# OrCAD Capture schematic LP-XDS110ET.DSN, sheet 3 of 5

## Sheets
3 3_EnergyTrace: size A3
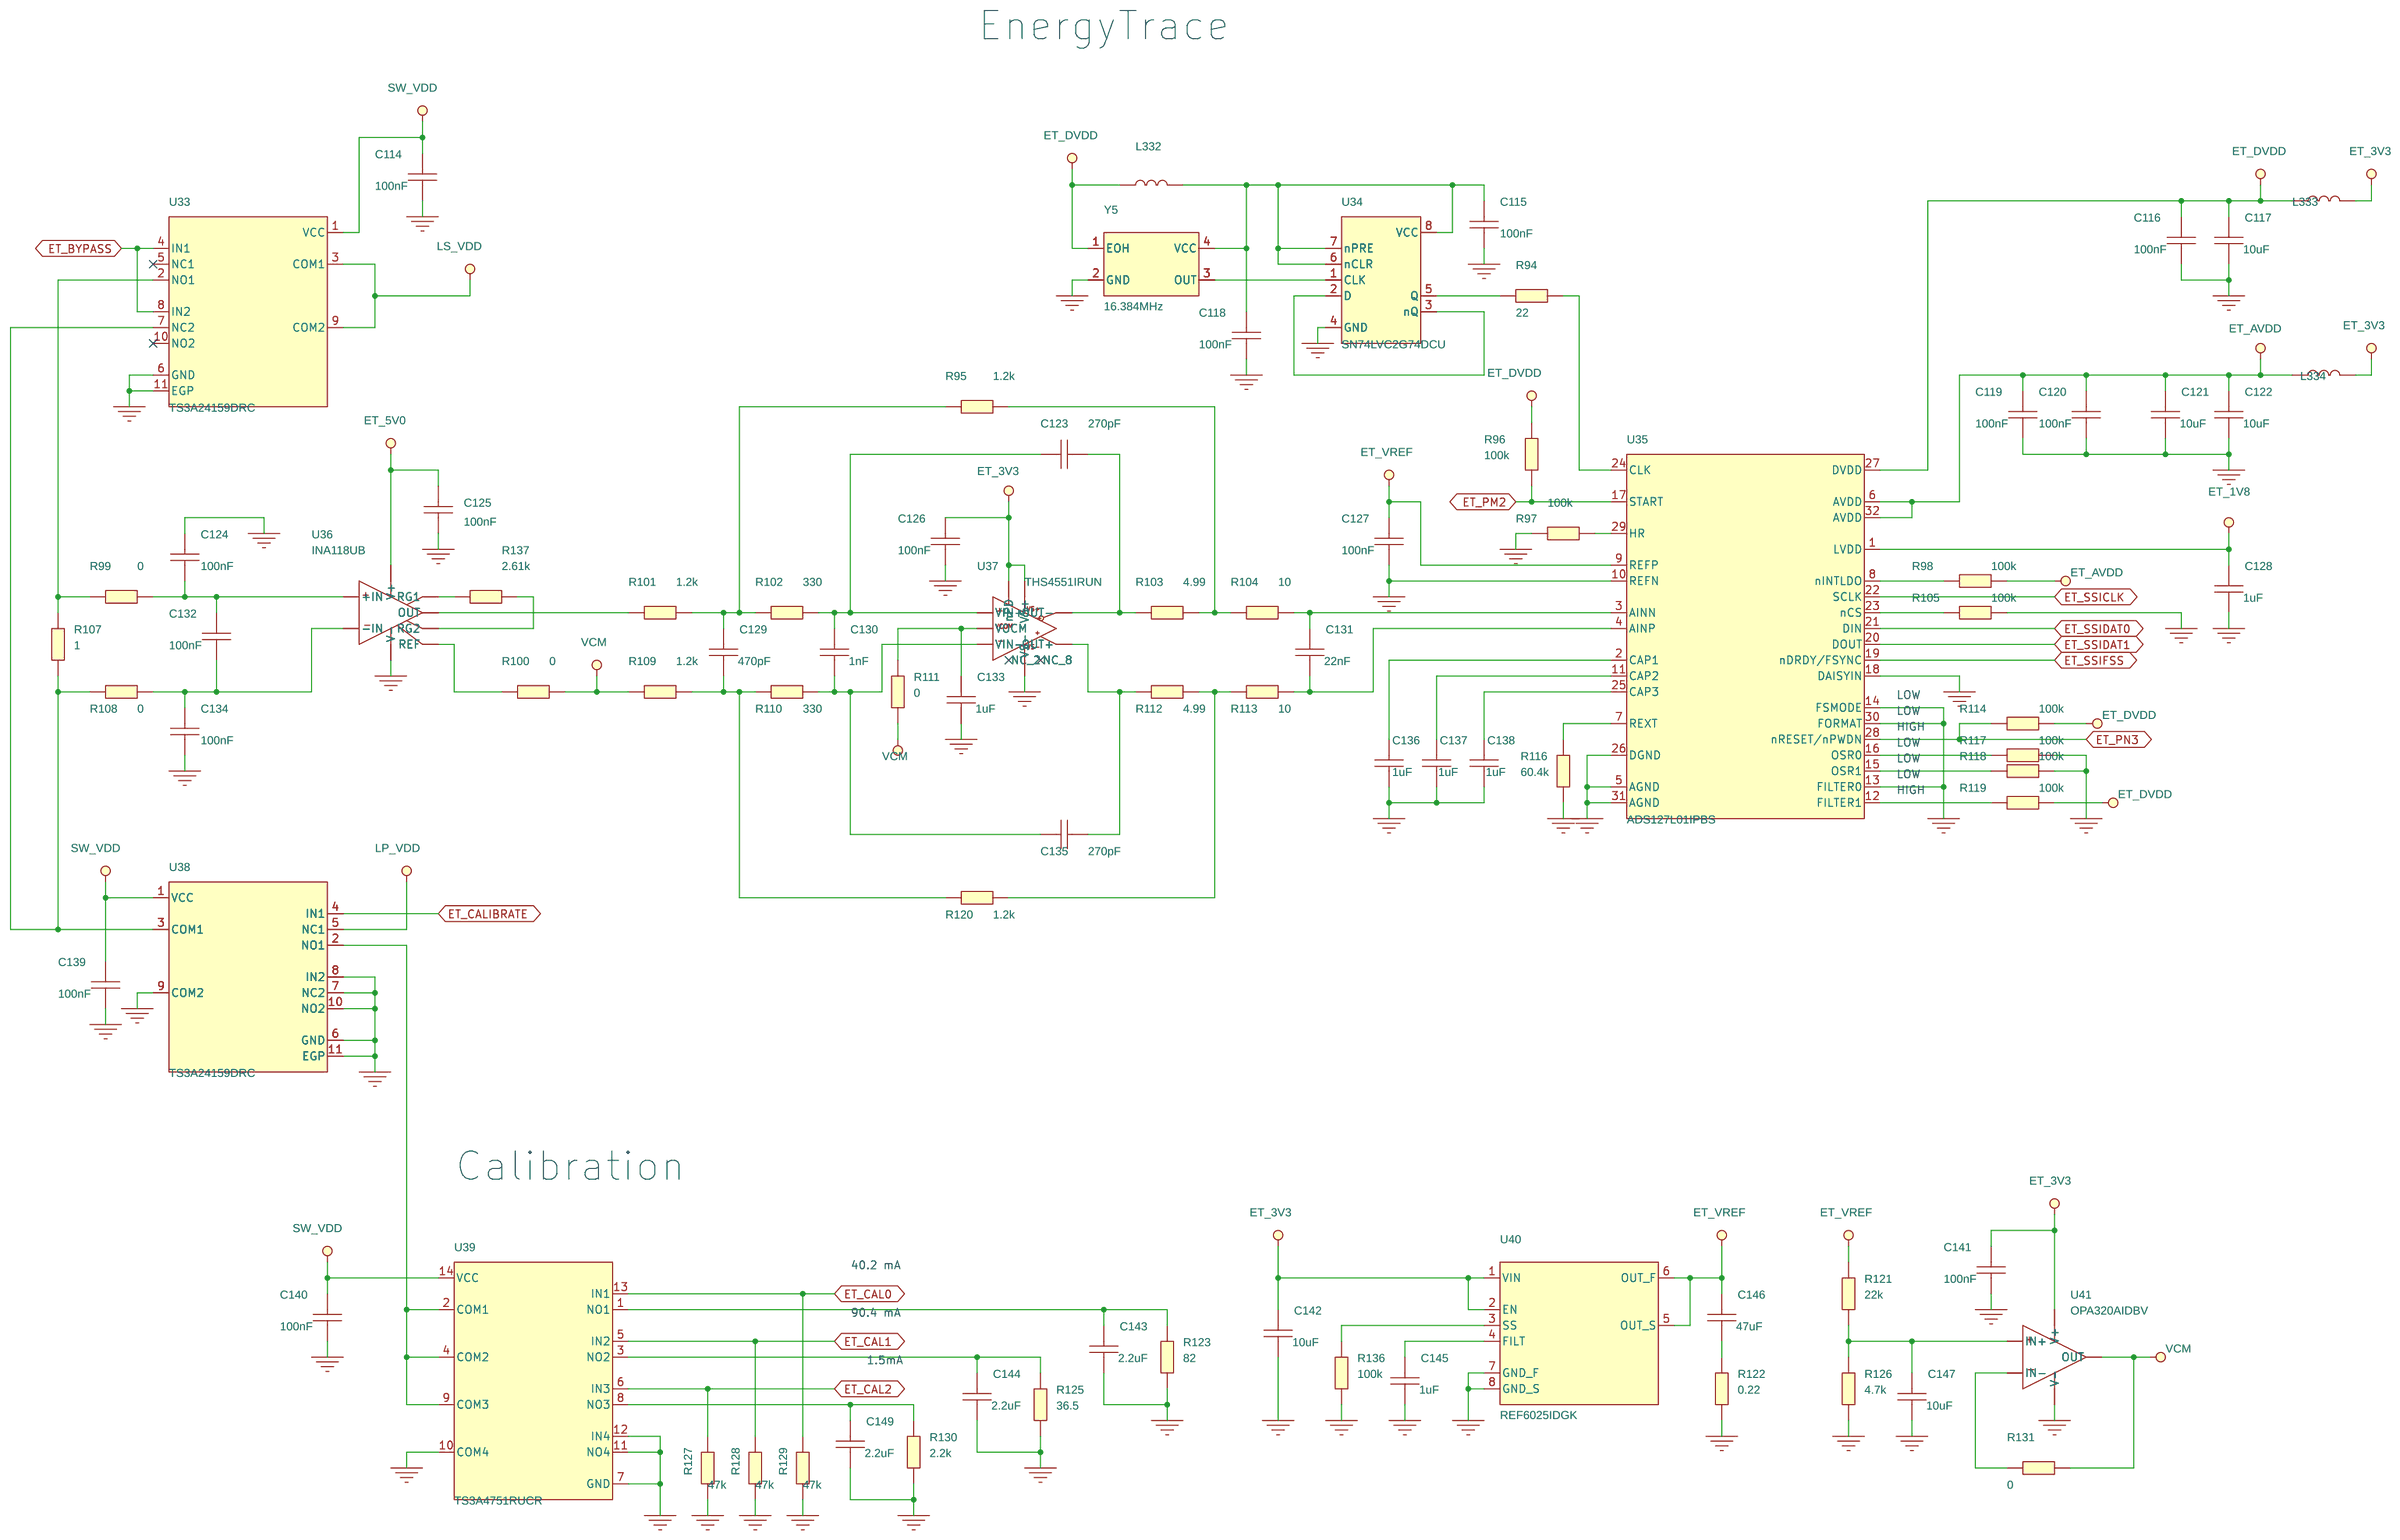
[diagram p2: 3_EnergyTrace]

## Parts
C114  100nF  [CAPC0603X35B2N]
C115  100nF  [CAPC0603X35B2N]
C116  100nF  [CAPC0603X35B2N]
C117  10uF  [CAPC2012X150A2N]
C118  100nF  [CAPC0603X35B2N]
C119  100nF  [CAPC0603X35B2N]
C120  100nF  [CAPC0603X35B2N]
C121  10uF  [CAPC2012X150A2N]
C122  10uF  [CAPC2012X150A2N]
C123  270pF  [CAPC1005X60B2N]
C124  100nF  [CAPC0603X35B2N]
C125  100nF  [CAPC0603X35B2N]
C126  100nF  [CAPC0603X35B2N]
C127  100nF  [CAPC0603X35B2N]
C128  1uF  [CAPC1005X60B2N]
C129  470pF  [CAPC1005X60A2N]
C130  1nF  [CAPC1005X60A2N]
C131  22nF  [CAPC1005X60A2N]
C132  100nF  [CAPC0603X35B2N]
C133  1uF  [CAPC1005X60B2N]
C134  100nF  [CAPC0603X35B2N]
C135  270pF  [CAPC1005X60B2N]
C136  1uF  [CAPC1005X60B2N]
C137  1uF  [CAPC1005X60B2N]
C138  1uF  [CAPC1005X60B2N]
C139  100nF  [CAPC0603X35B2N]
C140  100nF  [CAPC0603X35B2N]
C141  100nF  [CAPC0603X35B2N]
C142  10uF  [CAPC2012X150A2N]
C143  2.2uF  [CAPC1005X60A2N]
C144  2.2uF  [CAPC1005X60A2N]
C145  1uF  [CAPC1005X60B2N]
C146  47uF  [CAPC2012X150A2N]
C147  10uF  [CAPC2012X150A2N]
C149  2.2uF  [CAPC1005X60A2N]
L332  BLM21PG221SN1  [FILC2012X110A2N]
L333  BLM21PG221SN1  [FILC2012X110A2N]
L334  BLM21PG221SN1  [FILC2012X110A2N]
R94  22  [RESC1005X40A2N]
R95  1.2k  [RESC1005X40A2N]
R96  100k  [RESC1005X40B2N]
R97  100k  [RESC1005X40B2N]
R98  100k  [RESC1005X40B2N]
R99  0  [RESC1005X40B2N]
R100  0  [RESC1005X40B2N]
R101  1.2k  [RESC1005X40A2N]
R102  330  [RESC1005X40A2N]
R103  4.99  [RESC1005X40A2N]
R104  10  [RESC1005X40A2N]
R105  100k  [RESC1005X40B2N]
R107  1  [RESC3246X70A2N]
R108  0  [RESC1005X40B2N]
R109  1.2k  [RESC1005X40A2N]
R110  330  [RESC1005X40A2N]
R111  0  [RESC1005X40B2N]
R112  4.99  [RESC1005X40A2N]
R113  10  [RESC1005X40A2N]
R114  100k  [RESC1005X40B2N]
R116  60.4k  [RESC1005X40A2N]
R117  100k  [RESC1005X40B2N]
R118  100k  [RESC1005X40B2N]
R119  100k  [RESC1005X40B2N]
R120  1.2k  [RESC1005X40A2N]
R121  22k  [RESC1005X40A2N]
R122  0.22  [RESC1005X50A2N]
R123  82  [RESC3216X75A2N]
R125  36.5  [RESC3225X75A2N]
R126  4.7k  [RESC1005X40B2N]
R127  47k  [RESC1005X40A2N]
R128  47k  [RESC1005X40A2N]
R129  47k  [RESC1005X40A2N]
R130  2.2k  [RESC1005X40A2N]
R131  0  [RESC1005X40B2N]
R136  100k  [RESC1005X40B2N]
R137  2.61k  [RESC1005X40A2N]
U33  TS3A24159DRC  [SON50P300X300X100-11A2N]
U34  SN74LVC2G74DCU  [SOP50P310X90-8N]
U35  ADS127L01IPBS  [QFP50P700X700X120-32A2N]
U36  INA118UB  [SOIC127P600X175-8N]
U37  THS4551IRUN  [QFNFCP50P200X200X80-10A2N]
U38  TS3A24159DRC  [SON50P300X300X100-11A2N]
U39  TS3A4751RUCR  [QFNFC40P200X200X40-14A2N]
U40  REF6025IDGK  [SOP65P490X110-8A2N]
U41  OPA320AIDBV  [SOT95P280X145-5A2N]
Y5  16.384MHz  [OSCSC254P320X500X130-4A2N]

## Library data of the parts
C114-C116 C118-C120 C124-C127 C132 C134 C139-C141 = CAPACITOR: CAPACITOR, CERAMIC X5R, 100nF, 10V, -10%/+10%, -55DEGC/+85DEGC, 0201, SMD; ALT_SYMBOLS: CAPC0603X35B2L,CAPC0603X35B2M; Additional Datasheet URL: http://psearch.en.murata.com/capacitor/product/GRM033R61A104KE84%23.html; AutoDoc File: https://notefied-dynamic-precision.com/DB/Apps/Desktop/Item/Object.aspx?id=96679; BU Name: DYNAMIC PRECISION GDANSK; Budget Currency: EUR; Budget Price: 0.008; Budgetary Price: 0.008 EUR; Client Status: UNDER_REVIEW; Country of Origin: Missing Info; Datasheet URL: http://psearch.murata.com/capacitor/product/GRM033R61A104KE84%23.pdf; Datasheet URL 1: http://psearch.murata.com/capacitor/product/GRM033R61A104KE84%23.pdf; Datasheet URL 2: http://search.murata.co.jp/Ceramy/image/img/w_hinm/L0005E.pdf; Dielectric Type: X5R; Lead Time: 17; LifeCycle Status: ACTIVE; MPN: GRM155R70J104KA01D; MPN Status: ACTIVE; Manufacturer: MURATA; Mass: 0.00033g; Max Oper Temp: +85DEGC; Max Tol: +10%; Maximum Operating Temperature: +85DEGC; Maximum Tolerance: +10%; Min Oper Temp: -55DEGC; Min Tol: -10%; Minimum Operating Temperature: -55DEGC; Minimum Tolerance: -10%; Mounting Type: SMD; NOTE Status: PREFERRED; NOTEfied URL: https://notefied-dynamic-precision.com/NOTEfiedWebInterface/part/show?partNumber=02-06085; Old Footprint: CAPC1005X60N,0402; PCB Package: 0201; Packing Size: 15000; Packing Type: Tape & Reel; Part Number: 02-06085; Part Type: Capacitor|CERAMIC|0201|STANDARD; REACH/SVHC Compliance: Compliant; REACH/SVHC Details: SVHC List Version Jul 7, 2017; REACH/SVHC Source: REACH Declaration; REACH/SVHC Status: Unaffected; REACH/SVHC_COMPLIANCE: COMPLIANT; REACH/SVHC_DETAILS: SVHC LIST VERSION Jun 20, 2016; REACH/SVHC_SOURCE: REACH DECLARATION; REACH/SVHC_STATUS: UNAFFECTED; ROHS: Compliant; Rated Voltage: 10V; Revision: R011; RoHS Status: ROHS_COMPLIANT; Rtd Voltage: 10V; Status: Released; Texas Part Status: Under Review; Type: Capacitor; Vendor: MURATA; Vendor Part Number: GRM033R61A104KE84D; Vendor Part Status: Active; WEIGHT: 0.00033g
C117 C121 C122 C142 C147 = CAPACITOR: CAPACITOR, CERAMIC X7R, 10uF, 16V, -10%/+10%, -55DEGC/+125DEGC, 0805, SMD; ALT_SYMBOLS: CAPC2012X150A2L,CAPC2012X150A2M; Additional Datasheet URL: http://www.samsungsem.com/kr/support/product-search/mlcc/__icsFiles/afieldfile/2016/08/18/S_CL21B106KOQNNNE.pdf; AutoDoc File: https://notefied-dynamic-precision.com/DB/Apps/Desktop/Item/Object.aspx?id=94511; BU Name: DYNAMIC PRECISION GDANSK; Budget Currency: USD; Budget Price: 0.05; Budgetary Price: 0.05 USD; Client Status: UNDER_REVIEW; Country of Origin: South Korea; Datasheet URL: http://www.samsungsem.com/kr/support/library/product-catalog/__icsFiles/afieldfile/2016/09/27/MLCC.pdf; Datasheet URL 1: http://www.samsungsem.com/kr/front/downloadcms.do?path=/kr/support/product-search/mlcc/__icsFiles/afieldfile/2015/10/15&fileName=S_CL21B106KOQNNNE.pdf; Datasheet URL 2: N/A; Dielectric Type: X7R; Lead Time: 11; Mass: 0.0166g; Max Oper Temp: +125DEGC; Max Tol: +10%; Maximum Operating Temperature: +125DEGC; Maximum Tolerance: +10%; Min Oper Temp: -55DEGC; Min Tol: -10%; Minimum Operating Temperature: -55DEGC; Minimum Tolerance: -10%; Mounting Type: SMD; NOTEfied URL: https://notefied-dynamic-precision.com/NOTEfiedWebInterface/part/show?partNumber=02-05775; PCB Package: 0805; Packing Size: 2000; Packing Type: Tape & Reel; Part Number: 02-05775; Part Type: Capacitor|CERAMIC|0805|STANDARD; REACH/SVHC Compliance: Compliant; REACH/SVHC Details: SVHC List Version Jan 12, 2017; REACH/SVHC Source: REACH Declaration; REACH/SVHC Status: Unaffected; ROHS: Compliant; Rated Voltage: 16V; Revision: R007; RoHS Status: ROHS_COMPLIANT; Rtd Voltage: 16V; Status: Released; Texas Part Status: Under Review; Type: Capacitor; Vendor: SAMSUNG ELECTRO-MECHANICS; Vendor Part Number: CL21B106KOQNNNE; Vendor Part Status: Active; Weight: 0.0166g
C123 C135 = CAPACITOR: CAPACITOR, CERAMIC C0G/NP0, 270pF, 50V, -1%/+1%, -55DEGC/+125DEGC, 0402, SMD; Additional Datasheet URL: http://psearch.en.murata.com/capacitor/product/GRM1555C1H271FA01%23.html; Datasheet URL: http://psearch.en.murata.com/capacitor/product/GRM1555C1H271FA01%23.pdf; Dielectric Type: C0G/NP0; Mass: 0.0016g; Maximum Operating Temperature: +125DEGC; Maximum Tolerance: +1%; Minimum Operating Temperature: -55DEGC; Minimum Tolerance: -1%; Mounting Type: SMD; NOTEfied URL: https://notefied-dynamic-precision.com/NOTEfiedWebInterface/part/show?partNumber=02-08708; PCB Package: 0402; Packing Size: 10000; Packing Type: Tape & Reel; Part Number: 02-08708; Part Type: Capacitor|CERAMIC|0402|PRECISION; REACH/SVHC Compliance: Compliant; REACH/SVHC Details: SVHC List Version Jul 7, 2017; REACH/SVHC Source: REACH Declaration; REACH/SVHC Status: Unaffected; ROHS: Compliant; Rated Voltage: 50V; Revision: R001; Status: Released; Texas Part Status: Under Review; Type: Capacitor; Vendor: MURATA; Vendor Part Number: GRM1555C1H271FA01D; Vendor Part Status: Active
C128 C133 C136-C138 C145 = CAPACITOR: CAPACITOR, CERAMIC X5R, 1uF, 16V, -10%/+10%, -55DEGC/+85DEGC, 0402, SMD; Additional Datasheet URL: http://psearch.en.murata.com/capacitor/product/GRM155R61C105KA12%23.html; AutoDoc File: https://notefied-dynamic-precision.com/DB/Apps/Desktop/Item/Object.aspx?id=115295; BU Name: TEXAS INSTRUMENTS NORWAY; Client Status: UNDER_REVIEW; Datasheet URL: http://psearch.murata.com/capacitor/product/GRM155R61C105KA12%23.pdf; Datasheet URL 1: http://psearch.en.murata.com/capacitor/product/GRM155R61C105KA12%23.pdf; Datasheet URL 2: http://search.murata.co.jp/Ceramy/image/img/w_hinm/L0005E.pdf; Definied Quality: INDUSTRIAL; Dielectric Type: X5R; Esd Level: N/A; MPN: GRM155R61A105KE15D; MPN Status: ACTIVE; MSL: 1; MTBF: N/A; MTBF Standard: N/A; Manufacturer: MURATA; Mass: 0.0016g; Max Oper Temp: +85DEGC; Max Tol: +10%; Maximum Operating Temperature: +85DEGC; Maximum Tolerance: +10%; Min Oper Temp: -55DEGC; Min Tol: -10%; Minimum Operating Temperature: -55DEGC; Minimum Tolerance: -10%; Mounting Type: SMD; NOTE Status: PREFERRED; NOTEfied URL: https://notefied-dynamic-precision.com/NOTEfiedWebInterface/part/show?partNumber=02-07863; Old Footprint: CAPC1005X60N,0402; PCB Package: 0402; Packing Size: 10000; Packing Type: Tape & Reel; Part Number: 02-07863; Part Type: Capacitor|CERAMIC|0402|STANDARD; REACH/SVHC Compliance: Compliant; REACH/SVHC Details: SVHC List Version Jul 7, 2017; REACH/SVHC Source: REACH Declaration; REACH/SVHC Status: Unaffected; REACH/SVHC_COMPLIANCE: COMPLIANT; REACH/SVHC_DETAILS: SVHC LIST VERSION Jun 20, 2016; REACH/SVHC_SOURCE: REACH DECLARATION; REACH/SVHC_STATUS: UNAFFECTED; ROHS: Compliant; Rated Voltage: 16V; Revision: R008; RoHS Status: ROHS_COMPLIANT; Rtd Voltage: 16V; Status: Released; Texas Part Status: Under Review; Type: Capacitor; Vendor: MURATA; Vendor Part Number: GRM155R61C105KA12D; Vendor Part Status: Active; WEIGHT: 0.0016g
C129 = CAPACITOR: CAPACITOR, CERAMIC X7R, 470pF, 50V, -10%/+10%, -55DEGC/+125DEGC, 0402, SMD; ALT_SYMBOLS: CAPC1005X60A2L,CAPC1005X60A2M; Additional Datasheet URL: http://search.murata.co.jp/Ceramy/image/img/w_hinm/L0005E.pdf; Budgetary Price: 0.009 EUR; Country of Origin: Philippines; Datasheet URL: http://psearch.murata.com/capacitor/product/GRM155R71H471KA01%23.pdf; Dielectric Type: X7R; Lead Time: 18; Mass: 0.0016g; Maximum Operating Temperature: +125DEGC; Maximum Tolerance: +10%; Minimum Operating Temperature: -55DEGC; Minimum Tolerance: -10%; Mounting Type: SMD; NOTEfied URL: https://notefied-dynamic-precision.com/NOTEfiedWebInterface/part/show?partNumber=02-00613; PCB Package: 0402; Packing Size: 10000; Packing Type: Tape & Reel; Part Number: 02-00613; Part Type: Capacitor|CERAMIC|0402|STANDARD; REACH/SVHC Compliance: Compliant; REACH/SVHC Details: SVHC List Version Jul 07, 2017; REACH/SVHC Source: REACH Declaration; REACH/SVHC Status: Unaffected; ROHS: Compliant; Rated Voltage: 50V; Revision: R006; Status: Released; Texas Part Status: Under Review; Type: Capacitor; Vendor: MURATA; Vendor Part Number: GRM155R71H471KA01D; Vendor Part Status: Active
C130 = CAPACITOR: CAPACITOR, CERAMIC X7R, 1nF, 50V, -10%/+10%, -55DEGC/+125DEGC, 0402, SMD; ALT_SYMBOLS: CAPC1005X60A2L,CAPC1005X60A2M; Additional Datasheet URL: http://psearch.en.murata.com/capacitor/product/GRM155R71H102KA01%23.html; Budgetary Price: 0.003 EUR; Country of Origin: China; Datasheet URL: http://psearch.murata.com/capacitor/product/GRM155R71H102KA01%23.pdf; Dielectric Type: X7R; Lead Time: 18; Mass: 0.0016g; Maximum Operating Temperature: +125DEGC; Maximum Tolerance: +10%; Minimum Operating Temperature: -55DEGC; Minimum Tolerance: -10%; Mounting Type: SMD; NOTEfied URL: https://notefied-dynamic-precision.com/NOTEfiedWebInterface/part/show?partNumber=02-02070; PCB Package: 0402; Packing Size: 10000; Packing Type: Tape & Reel; Part Number: 02-02070; Part Type: Capacitor|CERAMIC|0402|STANDARD; REACH/SVHC Compliance: Compliant; REACH/SVHC Details: SVHC List Version Jul 7, 2017; REACH/SVHC Source: REACH Declaration; REACH/SVHC Status: Unaffected; ROHS: Compliant; Rated Voltage: 50V; Revision: R013; Status: Released; Texas Part Status: Under Review; Type: Capacitor; Vendor: MURATA; Vendor Part Number: GRM155R71H102KA01D; Vendor Part Status: Active
C131 = CAPACITOR: CAPACITOR, CERAMIC X7R, 22nF, 25V, -10%/+10%, -55DEGC/+125DEGC, 0402, SMD; ALT_SYMBOLS: CAPC1005X60A2L,CAPC1005X60A2M; Additional Datasheet URL: http://psearch.en.murata.com/capacitor/product/GRM155R71E223KA61%23.html; Budgetary Price: 0.01 EUR; Country of Origin: Philippines; Datasheet URL: http://psearch.murata.com/capacitor/product/GRM155R71E223KA61%23.pdf; Dielectric Type: X7R; Lead Time: 18; Mass: 0.0016g; Maximum Operating Temperature: +125DEGC; Maximum Tolerance: +10%; Minimum Operating Temperature: -55DEGC; Minimum Tolerance: -10%; Mounting Type: SMD; NOTEfied URL: https://notefied-dynamic-precision.com/NOTEfiedWebInterface/part/show?partNumber=02-05294; PCB Package: 0402; Packing Size: 10000; Packing Type: Tape & Reel; Part Number: 02-05294; Part Type: Capacitor|CERAMIC|0402|STANDARD; REACH/SVHC Compliance: Compliant; REACH/SVHC Details: SVHC List Version Jul 07, 2017; REACH/SVHC Source: REACH Declaration; REACH/SVHC Status: Unaffected; ROHS: Compliant; Rated Voltage: 25V; Revision: R007; Status: Released; Texas Part Status: Under Review; Type: Capacitor; Vendor: MURATA; Vendor Part Number: GRM155R71E223KA61D; Vendor Part Status: Active
C143 C144 C149 = CAPACITOR: CAPACITOR, CERAMIC X5R, 2.2uF, 25V, -10%/+10%, -55DEGC/+85DEGC, 0402, SMD; ALT_SYMBOLS: CAPC1005X60A2L,CAPC1005X60A2M; Additional Datasheet URL: http://search.murata.co.jp/Ceramy/image/img/w_hinm/L0005E.pdf; AutoDoc File: https://notefied-dynamic-precision.com/DB/Apps/Desktop/Item/Object.aspx?id=96297; BU Name: DYNAMIC PRECISION GDANSK; Budget Currency: EUR; Budget Price: 0.063; Budgetary Price: 0.063 EUR; Client Status: UNDER_REVIEW; Country of Origin: Missing Info; Datasheet URL: http://psearch.murata.com/capacitor/product/GRM155R61E225KE11%23.pdf; Datasheet URL 1: http://psearch.murata.com/capacitor/product/GRM155R61E225KE11%23.pdf; Datasheet URL 2: http://search.murata.co.jp/Ceramy/image/img/w_hinm/L0005E.pdf; Dielectric Type: X5R; Lead Time: 19; Mass: 0.0031g; Max Oper Temp: +85DEGC; Max Tol: +10%; Maximum Operating Temperature: +85DEGC; Maximum Tolerance: +10%; Min Oper Temp: -55DEGC; Min Tol: -10%; Minimum Operating Temperature: -55DEGC; Minimum Tolerance: -10%; Mounting Type: SMD; NOTEfied URL: https://notefied-dynamic-precision.com/NOTEfiedWebInterface/part/show?partNumber=02-06058; PCB Package: 0402; Packing Size: 10000; Packing Type: Tape & Reel; Part Number: 02-06058; Part Type: Capacitor|CERAMIC|0402|STANDARD; REACH/SVHC Compliance: Compliant; REACH/SVHC Details: SVHC List Version Jul 7, 2017; REACH/SVHC Source: REACH Declaration; REACH/SVHC Status: Unaffected; REACH/SVHC_COMPLIANCE: COMPLIANT; REACH/SVHC_DETAILS: SVHC List Version Jun 20, 2016; REACH/SVHC_SOURCE: REACH DECLARATION; REACH/SVHC_STATUS: UNAFFECTED; ROHS: Compliant; Rated Voltage: 25V; Revision: R007; RoHS Status: ROHS_COMPLIANT; Rtd Voltage: 25V; Status: Released; Texas Part Status: Under Review; Type: Capacitor; Vendor: MURATA; Vendor Part Number: GRM155R61E225KE11D; Vendor Part Status: Active; Weight: 0.0031g
C146 = CAPACITOR: CAPACITOR, CERAMIC X5R, 47uF, 10V, -20%/+20%, -55DEGC/+85DEGC, 0805, SMD; ALT_SYMBOLS: CAPC2012X150A2L,CAPC2012X150A2M; Additional Datasheet URL: http://psearch.en.murata.com/capacitor/product/GRM21BR61A476ME15%23.html; AutoDoc File: https://notefied-dynamic-precision.com/DB/Apps/Desktop/Item/Object.aspx?id=94511; BU Name: DYNAMIC PRECISION GDANSK; Budget Currency: USD; Budget Price: 0.05; Client Status: UNDER_REVIEW; Datasheet URL: http://psearch.murata.com/capacitor/product/GRM21BR61A476ME15%23.pdf; Datasheet URL 1: http://www.samsungsem.com/kr/front/downloadcms.do?path=/kr/support/product-search/mlcc/__icsFiles/afieldfile/2015/10/15&fileName=S_CL21B106KOQNNNE.pdf; Datasheet URL 2: N/A; Dielectric Type: X5R; Mass: 0.023g; Max Oper Temp: +125DEGC; Max Tol: +10%; Maximum Operating Temperature: +85DEGC; Maximum Tolerance: +20%; Min Oper Temp: -55DEGC; Min Tol: -10%; Minimum Operating Temperature: -55DEGC; Minimum Tolerance: -20%; Mounting Type: SMD; NOTEfied URL: https://notefied-dynamic-precision.com/NOTEfiedWebInterface/part/show?partNumber=02-07728; PCB Package: 0805; Packing Size: 3000; Packing Type: Tape & Reel; Part Number: 02-07728; Part Type: Capacitor|CERAMIC|0805|STANDARD; REACH/SVHC Compliance: Compliant; REACH/SVHC Details: SVHC List Version Jul 7, 2017; REACH/SVHC Source: REACH Declaration; REACH/SVHC Status: Unaffected; ROHS: Compliant; Rated Voltage: 10V; Revision: R008; RoHS Status: ROHS_COMPLIANT; Rtd Voltage: 16V; Status: Released; Texas Part Status: Under Review; Type: Capacitor; Vendor: MURATA; Vendor Part Number: GRM21BR61A476ME15L; Vendor Part Status: Active; Weight: 0.0166g
L332-L334 = INDUCTOR: FILTER, EMI, FERRITE BEAD, 220@100MHz, -25%/+25%, -55DEGC/+125DEGC, 0805, SMD; ALT_SYMBOLS: FILC2012X110A2L,FILC2012X110A2M; Additional Datasheet URL: http://www.murata.com/en-global/products/productdetail.aspx?cate=luNoiseSupprFilteChipFerriBead&partno=BLM21PG221SN1%23; AutoDoc File: https://notefied-dynamic-precision.com/DB/Apps/Desktop/Item/Object.aspx?id=15278; BU Name: DYNAMIC PRECISION GDANSK; Budget Currency: EUR; Budget Price: 0.03; Budgetary Price: 0.03 EUR; Client Status: UNDER_REVIEW; Country of Origin: Japan,Singapore,Thailand; Datasheet URL: http://www.murata.com/en-global/api/pdfdownloadapi?cate=luNoiseSupprFilteChipFerriBead&partno=BLM21PG221SN1%23; Datasheet URL 1: http://search.murata.co.jp/Ceramy/image/img/PDF/ENG/L0110S0100BLM21P.pdf; Datasheet URL 2: http://search.murata.co.jp/Ceramy/image/img/w_hinm/L0110E.pdf; Frequency: 100MHz; Impedance: 220; Inductance: N/A; Lead Time: 9; Mass: 0.0098g; Max Oper Temp: +125DEGC; Max Tol: +25%; Maximum Operating Temperature: +125DEGC; Maximum Tolerance: +25%; Min Oper Temp: -55DEGC; Min Tol: -25%; Minimum Operating Temperature: -55DEGC; Minimum Tolerance: -25%; Mounting Type: SMD; NOTEfied URL: https://notefied-dynamic-precision.com/NOTEfiedWebInterface/part/show?partNumber=04-00050; PCB Package: 0805; Packing Size: 4000; Packing Type: Tape & Reel; Part Number: 04-00050; Part Type: Filter|EMI|FERRITE BEAD|0805; REACH/SVHC Compliance: Compliant; REACH/SVHC Details: SVHC List Version Jul 7, 2017; REACH/SVHC Source: REACH Declaration; REACH/SVHC Status: Unaffected; ROHS: Compliant; Rated Current: 2A; Rated Voltage: N/A; Resistance: 0.045; Revision: R011; RoHS Status: ROHS_COMPLIANT; Rtd Current: 2A; Rtd Voltage: N/A; Status: Released; Texas Part Status: Under Review; Type: Filter; Vendor: MURATA; Vendor Part Number: BLM21PG221SN1D; Vendor Part Status: Active; Weight: 0.0098g
R94 = RESISTOR: RESISTOR, THICK FILM, 22, -5%/+5%, 0.063W, 50V, -55DEGC/+155DEGC, 0402, SMD; ALT_SYMBOLS: RESC1005X40A2L,RESC1005X40A2M; Additional Datasheet URL: N/A; AutoDoc File: https://notefied-dynamic-precision.com/DB/Apps/Desktop/Item/Object.aspx?id=47067; BU Name: DYNAMIC PRECISION GDANSK; Budget Currency: EUR; Budget Price: 0.014; Budgetary Price: 0.014 EUR; Country of Origin: Israel; Datasheet URL: http://www.vishay.com/docs/20035/dcrcwe3.pdf; Datasheet URL 1: http://www.vishay.com/docs/20035/dcrcwe3.pdf; Datasheet URL 2: N/A; Lead Time: 18; Mass: 0.00065g; Max Oper Temp: +155DEGC; Max TC: +200PPM/DEGC; Max Tol: +5%; Maximum Operating Temperature: +155DEGC; Maximum Temperature Coefficient: +200PPM/DEGC; Maximum Tolerance: +5%; Min Oper Temp: -55DEGC; Min TC: -200PPM/DEGC; Min Tol: -5%; Minimum Operating Temperature: -55DEGC; Minimum Temperature Coeficient: -200PPM/DEGC; Minimum Tolerance: -5%; Mounting Type: SMD; NOTEfied URL: https://notefied-dynamic-precision.com/NOTEfiedWebInterface/part/show?partNumber=01-01183; PCB Package: 0402; Packing Size: 10000; Packing Type: Tape & Reel; Part Number: 01-01183; Part Type: Resistor|0402|STANDARD; REACH/SVHC Compliance: Compliant; REACH/SVHC Details: SVHC List Version Jun 20, 2016; REACH/SVHC Source: Material Declaration; REACH/SVHC Status: Unaffected; ROHS: Exempt; Rated Current: N/A; Rated Power: 0.063W; Rated Voltage: 50V; Resistor Type: THICK FILM; Revision: R006; RoHS Status: ROHS_COMPLIANT; Rtd Current: N/A; Rtd Power: 0.063W; Rtd Voltage: 50V; Status: Released; Texas Part Status: Under Review; Type: Resistor; Vendor: VISHAY; Vendor Part Number: CRCW040222R0JNED; Vendor Part Status: Active; Weight: 0.00065g
R95 R101 R109 R120 = RESISTOR: RESISTOR, THICK FILM, 1.2k, -1%/+1%, 0.063W, 50V, -55DEGC/+155DEGC, 0402, SMD; ALT_SYMBOLS: RESC1005X40A2L,RESC1005X40A2M; Additional Datasheet URL: N/A; Budgetary Price: 0.012 EUR; Country of Origin: Israel; Datasheet URL: http://www.vishay.com/docs/20035/dcrcwe3.pdf; Lead Time: 14; Mass: 0.00065g; Maximum Operating Temperature: +155DEGC; Maximum Temperature Coefficient: +100PPM/DEGC; Maximum Tolerance: +1%; Minimum Operating Temperature: -55DEGC; Minimum Temperature Coeficient: -100PPM/DEGC; Minimum Tolerance: -1%; Mounting Type: SMD; NOTEfied URL: https://notefied-dynamic-precision.com/NOTEfiedWebInterface/part/show?partNumber=01-00128; PCB Package: 0402; Packing Size: 10000; Packing Type: Tape & Reel; Part Number: 01-00128; Part Type: Resistor|0402|PRECISION; REACH/SVHC Compliance: Compliant; REACH/SVHC Details: SVHC List Version Jul 07, 2017; REACH/SVHC Source: REACH Declaration; REACH/SVHC Status: Unaffected; ROHS: Exempt; Rated Current: N/A; Rated Power: 0.063W; Rated Voltage: 50V; Resistor Type: THICK FILM; Revision: R011; Status: Released; Texas Part Status: Under Review; Type: Resistor; Vendor: VISHAY; Vendor Part Number: CRCW04021K20FKED; Vendor Part Status: Active
R96-R98 R105 R114 R117-R119 R136 = RESISTOR: RESISTOR, THICK FILM, 100k, -1%/+1%, 0.063W, 50V, -55DEGC/+155DEGC, 0402, SMD; Additional Datasheet URL: http://www.ttelectronics.com/resistors/parts/wcr0402; AutoDoc File: https://notefied-dynamic-precision.com/DB/Apps/Desktop/Item/Object.aspx?id=115161; BU Name: TEXAS INSTRUMENTS NORWAY; Client Status: UNDER_REVIEW; Datasheet URL: http://www.ttelectronicsresistors.com/datasheets/WCR.pdf; Datasheet URL 1: http://www.ttelectronicsresistors.com/datasheets/WCR.pdf; Definied Quality: INDUSTRIAL; Esd Level: N/A; LifeCycle Status: ACTIVE; MPN: RESISTOR_0402_100k_+/-1%_50V_0.063W_M_+/-100PPM; MPN Status: ACTIVE; MSL: N/A; MTBF: N/A; MTBF Standard: N/A; Manufacturer: MANUFACTURER SELECTION; Max Oper Temp: +155DEGC; Max TC: +100PPM/DEGC; Max Tol: +1%; Maximum Operating Temperature: +155DEGC; Maximum Temperature Coefficient: +100PPM/DEGC; Maximum Tolerance: +1%; Min Oper Temp: -55DEGC; Min TC: -100PPM/DEGC; Min Tol: -1%; Minimum Operating Temperature: -55DEGC; Minimum Temperature Coeficient: -100PPM/DEGC; Minimum Tolerance: -1%; Mounting Type: SMD; NOTE Status: PREFERRED; NOTEfied URL: https://notefied-dynamic-precision.com/NOTEfiedWebInterface/part/show?partNumber=01-22536; Old Footprint: RESC1005X40N; PCB Package: 0402; Packing Size: 10000; Packing Type: Tape & Reel; Part Number: 01-22536; Part Type: Resistor|0402|PRECISION; REACH/SVHC Compliance: Compliant; REACH/SVHC Details: SVHC List Version Jun 20, 2016; REACH/SVHC Source: Material Declaration; REACH/SVHC Status: Unaffected; ROHS: Exempt; Rated Current: N/A; Rated Power: 0.063W; Rated Voltage: 50V; Resistor Type: THICK FILM; Revision: R007; RoHS Status: ROHS_COMPLIANT; Rtd Current: N/A; Rtd Power: 0.063W; Rtd Voltage: 50V; Status: Released; Texas Part Status: Under Review; Type: Resistor; Vendor: TT ELECTRONICS; Vendor Part Number: WCR0402-100KFA; Vendor Part Status: Active
R99 R100 R108 R111 = RESISTOR: RESISTOR, THICK FILM, 0, 0.063W, 50V, -55DEGC/+155DEGC, 0402, SMD; Additional Datasheet URL: N/A; AutoDoc File: https://notefied-dynamic-precision.com/DB/Apps/Desktop/Item/Object.aspx?id=114568; BU Name: TEXAS INSTRUMENTS NORWAY; Budget Currency: EUR; Budget Price: 0.007; Budgetary Price: 0.007 EUR; Client Status: UNDER_REVIEW; Country of Origin: Israel; Datasheet URL: http://www.vishay.com/docs/20035/dcrcwe3.pdf; Datasheet URL 1: http://www.vishay.com/docs/20035/dcrcwe3.pdf; Datasheet URL 2: N/A; Exclusive for Customers: TEXAS INSTRUMENTS NORWAY; Lead Time: 14; Mass: 0.0006152g; Max Oper Temp: +155DEGC; Max TC: N/A; Max Tol: N/A; Maximum Operating Temperature: +155DEGC; Maximum Temperature Coefficient: N/A; Maximum Tolerance: N/A; Min Oper Temp: -55DEGC; Min TC: N/A; Min Tol: N/A; Minimum Operating Temperature: -55DEGC; Minimum Temperature Coeficient: N/A; Minimum Tolerance: N/A; Mounting Type: SMD; NOTEfied URL: https://notefied-dynamic-precision.com/NOTEfiedWebInterface/part/show?partNumber=01-22495; Notes: Standard item: Duplicate Reason: custom footprint for TEXAS INSTRUMENTS NORWAY.; PCB Package: 0402; Packing Size: 10000; Packing Type: Tape & Reel; Part Number: 01-22495; Part Type: Resistor|0402|JUMPER; REACH/SVHC Compliance: Compliant; REACH/SVHC Details: SVHC List Version Jul 07, 2017; REACH/SVHC Source: REACH Declaration; REACH/SVHC Status: Unaffected; REACH/SVHC_COMPLIANCE: COMPLIANT; REACH/SVHC_DETAILS: SVHC LIST VERSION Dec 17, 2015; REACH/SVHC_SOURCE: MATERIAL DECLARATION; REACH/SVHC_STATUS: UNAFFECTED; ROHS: Exempt; Rated Current: N/A; Rated Power: 0.063W; Rated Voltage: 50V; Resistor Type: THICK FILM; Revision: R012; RoHS Status: ROHS_COMPLIANT_WITH_EXEMPTION; Rtd Current: N/A; Rtd Power: 0.063W; Rtd Voltage: 50V; Status: Released; Texas Part Status: Under Review; Type: Resistor; Vendor: VISHAY; Vendor Part Number: CRCW04020000Z0ED; Vendor Part Status: Active; Weight: 0.0006152g
R102 R110 = RESISTOR: RESISTOR, THICK FILM, 330, -1%/+1%, 0.063W, 50V, -55DEGC/+155DEGC, 0402, SMD; ALT_SYMBOLS: RESC1005X40A2L,RESC1005X40A2M; Additional Datasheet URL: N/A; Budgetary Price: 0.012 EUR; Country of Origin: Israel; Datasheet URL: http://www.vishay.com/docs/20035/dcrcwe3.pdf; Lead Time: 14; Mass: 0.00060916g; Maximum Operating Temperature: +155DEGC; Maximum Temperature Coefficient: +100PPM/DEGC; Maximum Tolerance: +1%; Minimum Operating Temperature: -55DEGC; Minimum Temperature Coeficient: -100PPM/DEGC; Minimum Tolerance: -1%; Mounting Type: SMD; NOTEfied URL: https://notefied-dynamic-precision.com/NOTEfiedWebInterface/part/show?partNumber=01-00195; PCB Package: 0402; Packing Size: 10000; Packing Type: Tape & Reel; Part Number: 01-00195; Part Type: Resistor|0402|PRECISION; REACH/SVHC Compliance: Compliant; REACH/SVHC Details: SVHC List Version Jul 07, 2017; REACH/SVHC Source: REACH Declaration; REACH/SVHC Status: Unaffected; ROHS: Exempt; Rated Current: N/A; Rated Power: 0.063W; Rated Voltage: 50V; Resistor Type: THICK FILM; Revision: R011; Status: Released; Texas Part Status: Under Review; Type: Resistor; Vendor: VISHAY; Vendor Part Number: CRCW0402330RFKED; Vendor Part Status: Active
R103 R112 = RESISTOR: RESISTOR, THICK FILM, 4.99, -1%/+1%, 0.063W, 50V, -55DEGC/+155DEGC, 0402, SMD; ALT_SYMBOLS: RESC1005X40A2L,RESC1005X40A2M; Additional Datasheet URL: N/A; Budgetary Price: 0.016 EUR; Country of Origin: Mexico; Datasheet URL: http://www.vishay.com/docs/20035/dcrcwe3.pdf; Lead Time: 18; Mass: 0.00065g; Maximum Operating Temperature: +155DEGC; Maximum Temperature Coefficient: +100PPM/DEGC; Maximum Tolerance: +1%; Minimum Operating Temperature: -55DEGC; Minimum Temperature Coeficient: -100PPM/DEGC; Minimum Tolerance: -1%; Mounting Type: SMD; NOTEfied URL: https://notefied-dynamic-precision.com/NOTEfiedWebInterface/part/show?partNumber=01-04307; PCB Package: 0402; Packing Size: 10000; Packing Type: Tape & Reel; Part Number: 01-04307; Part Type: Resistor|0402|PRECISION; REACH/SVHC Compliance: Compliant; REACH/SVHC Details: SVHC List Version Jul 07, 2017; REACH/SVHC Source: REACH Declaration; REACH/SVHC Status: Unaffected; ROHS: Exempt; Rated Current: N/A; Rated Power: 0.063W; Rated Voltage: 50V; Resistor Type: THICK FILM; Revision: R004; Status: Released; Texas Part Status: Under Review; Type: Resistor; Vendor: VISHAY; Vendor Part Number: CRCW04024R99FKED; Vendor Part Status: Active
R104 R113 = RESISTOR: RESISTOR, THICK FILM, 10, -1%/+1%, 0.063W, 50V, -55DEGC/+155DEGC, 0402, SMD; ALT_SYMBOLS: RESC1005X40A2L,RESC1005X40A2M; Additional Datasheet URL: N/A; Budgetary Price: 0.012 EUR; Country of Origin: Israel; Datasheet URL: http://www.vishay.com/docs/20035/dcrcwe3.pdf; FPLIST: RESC1005X40A2N,RESC1005X40C2N; Lead Time: 14; Mass: 0.00060916g; Maximum Operating Temperature: +155DEGC; Maximum Temperature Coefficient: +100PPM/DEGC; Maximum Tolerance: +1%; Minimum Operating Temperature: -55DEGC; Minimum Temperature Coeficient: -100PPM/DEGC; Minimum Tolerance: -1%; Mounting Type: SMD; NOTEfied URL: https://notefied-dynamic-precision.com/NOTEfiedWebInterface/part/show?partNumber=01-00234; PCB Package: 0402; Packing Size: 10000; Packing Type: Tape & Reel; Part Number: 01-00234; Part Type: Resistor|0402|PRECISION; REACH/SVHC Compliance: Compliant; REACH/SVHC Details: SVHC List Version Jul 07, 2017; REACH/SVHC Source: REACH Declaration; REACH/SVHC Status: Unaffected; ROHS: Exempt; Rated Current: N/A; Rated Power: 0.063W; Rated Voltage: 50V; Resistor Type: THICK FILM; Revision: R012; Status: Released; Texas Part Status: Under Review; Type: Resistor; Vendor: VISHAY; Vendor Part Number: CRCW040210R0FKED; Vendor Part Status: Active
R107 = RESISTOR: RESISTOR, THICK FILM, 1, -1%/+1%, 1W, 200V, -55DEGC/+155DEGC, 1218, SMD; ALT_SYMBOLS: RESC3246X70A2L,RESC3246X70A2M; Additional Datasheet URL: N/A; AutoDoc File: https://notefied-dynamic-precision.com/DB/Apps/Desktop/Item/Object.aspx?id=58334; BU Name: DYNAMIC PRECISION GDANSK; Budget Currency: USD; Budget Price: 0.1485; Budgetary Price: 0.1485 USD; Client Status: UNDER_REVIEW; Country of Origin: Israel; Datasheet URL: http://www.vishay.com/docs/20035/dcrcwe3.pdf; Datasheet URL 1: http://www.vishay.com/docs/20035/dcrcwe3.pdf; Datasheet URL 2: N/A; Lead Time: 10; Mass: 0.0295g; Max Oper Temp: +155DEGC; Max TC: +200PPM/DEGC; Max Tol: +1%; Maximum Operating Temperature: +155DEGC; Maximum Temperature Coefficient: +200PPM/DEGC; Maximum Tolerance: +1%; Min Oper Temp: -55DEGC; Min TC: -200PPM/DEGC; Min Tol: -1%; Minimum Operating Temperature: -55DEGC; Minimum Temperature Coeficient: -200PPM/DEGC; Minimum Tolerance: -1%; Mounting Type: SMD; NOTEfied URL: https://notefied-dynamic-precision.com/NOTEfiedWebInterface/part/show?partNumber=01-03527; PCB Package: 1218; Packing Size: 4000; Packing Type: Tape & Reel; Part Number: 01-03527; Part Type: Resistor|1218|PRECISION; REACH/SVHC Compliance: Compliant; REACH/SVHC Details: SVHC List Version Jun 20, 2016; REACH/SVHC Source: Material Declaration; REACH/SVHC Status: Unaffected; ROHS: Exempt; Rated Current: N/A; Rated Power: 1W; Rated Voltage: 200V; Resistor Type: THICK FILM; Revision: R010; RoHS Status: ROHS_COMPLIANT_WITH_EXEMPTION; Rtd Current: N/A; Rtd Power: 1W; Rtd Voltage: 200V; Status: Released; Texas Part Status: Under Review; Type: Resistor; Vendor: VISHAY; Vendor Part Number: CRCW12181R00FNEK; Vendor Part Status: Active; Weight: 0.0295g
R116 = RESISTOR: RESISTOR, THICK FILM, 60.4k, -1%/+1%, 0.063W, 50V, -55DEGC/+155DEGC, 0402, SMD; ALT_SYMBOLS: RESC1005X40A2L,RESC1005X40A2M; Additional Datasheet URL: N/A; AutoDoc File: https://notefied-dynamic-precision.com/DB/Apps/Desktop/Item/Object.aspx?id=59465; BU Name: DYNAMIC PRECISION GDANSK; Budget Currency: EUR; Budget Price: 0.012; Budgetary Price: 0.012 EUR; Client Status: UNDER_REVIEW; Country of Origin: Israel; Datasheet URL: http://www.vishay.com/docs/20035/dcrcwe3.pdf; Datasheet URL 1: http://www.vishay.com/docs/20035/dcrcwe3.pdf; Datasheet URL 2: N/A; Lead Time: 14; Mass: 0.00060916g; Max Oper Temp: +155DEGC; Max TC: +100PPM/DEGC; Max Tol: +1%; Maximum Operating Temperature: +155DEGC; Maximum Temperature Coefficient: +100PPM/DEGC; Maximum Tolerance: +1%; Min Oper Temp: -55DEGC; Min TC: -100PPM/DEGC; Min Tol: -1%; Minimum Operating Temperature: -55DEGC; Minimum Temperature Coeficient: -100PPM/DEGC; Minimum Tolerance: -1%; Mounting Type: SMD; NOTEfied URL: https://notefied-dynamic-precision.com/NOTEfiedWebInterface/part/show?partNumber=01-04658; PCB Package: 0402; Packing Size: 10000; Packing Type: Tape & Reel; Part Number: 01-04658; Part Type: Resistor|0402|PRECISION; REACH/SVHC Compliance: Compliant; REACH/SVHC Details: SVHC List Version Jun 20, 2016; REACH/SVHC Source: Material Declaration; REACH/SVHC Status: Unaffected; ROHS: Exempt; Rated Current: N/A; Rated Power: 0.063W; Rated Voltage: 50V; Resistor Type: THICK FILM; Revision: R012; RoHS Status: ROHS_COMPLIANT_WITH_EXEMPTION; Rtd Current: N/A; Rtd Power: 0.063W; Rtd Voltage: 50V; Status: Released; Texas Part Status: Under Review; Type: Resistor; Vendor: VISHAY; Vendor Part Number: CRCW040260K4FKED; Vendor Part Status: Active; Weight: 0.00060916g
R121 = RESISTOR: RESISTOR, THICK FILM, 22k, -5%/+5%, 0.063W, 50V, -55DEGC/+155DEGC, 0402, SMD; ALT_SYMBOLS: RESC1005X40A2L,RESC1005X40A2M; Additional Datasheet URL: N/A; AutoDoc File: https://notefied-dynamic-precision.com/DB/Apps/Desktop/Item/Object.aspx?id=113326; BU Name: TEXAS INSTRUMENTS NORWAY; Budget Currency: EUR; Budget Price: 0.014; Budgetary Price: 0.007 EUR; Client Status: UNDER_REVIEW; Country of Origin: Missing Info; Datasheet URL: http://www.vishay.com/docs/20035/dcrcwe3.pdf; Datasheet URL 1: http://www.vishay.com/docs/20035/dcrcwe3.pdf; Datasheet URL 2: N/A; Definied Quality: INDUSTRIAL; Esd Level: N/A; FPLIST: RESC1005X40A2N,RESC1005X40B2N; Lead Time: 14; LifeCycle Status: ACTIVE; MPN: RESISTOR_0402_10k_+/-5%_50V_0.063W_M_+/-200ppm; MPN Status: ACTIVE; MSL: N/A; MTBF: N/A; MTBF Standard: N/A; Manufacturer: MANUFACTURER SELECTION; Mass: 0.00065g; Max Oper Temp: +155DEGC; Max TC: +200PPM/DEGC; Max Tol: +5%; Maximum Operating Temperature: +155DEGC; Maximum Temperature Coefficient: +200PPM/DEGC; Maximum Tolerance: +5%; Min Oper Temp: -55DEGC; Min TC: -200PPM/DEGC; Min Tol: -5%; Minimum Operating Temperature: -55DEGC; Minimum Temperature Coeficient: -200PPM/DEGC; Minimum Tolerance: -5%; Mounting Type: SMD; NOTE Status: PREFERRED; NOTEfied URL: https://notefied-dynamic-precision.com/NOTEfiedWebInterface/part/show?partNumber=01-01252; Old Footprint: RESC1005X40N; PCB Package: 0402; Packing Size: 10000; Packing Type: Tape & Reel; Part Number: 01-01252; Part Type: Resistor|0402|STANDARD; REACH/SVHC Compliance: Compliant; REACH/SVHC Details: SVHC List Version Jul 07, 2017; REACH/SVHC Source: REACH Declaration; REACH/SVHC Status: Unaffected; REACH/SVHC_COMPLIANCE: COMPLIANT; REACH/SVHC_DETAILS: SVHC LIST VERSION Jun 20, 2016; REACH/SVHC_SOURCE: MATERIAL DECLARATION; REACH/SVHC_STATUS: UNAFFECTED; ROHS: Exempt; Rated Current: N/A; Rated Power: 0.063W; Rated Voltage: 50V; Resistor Type: THICK FILM; Revision: R004; RoHS Status: ROHS_COMPLIANT_WITH_EXEMPTION; Rtd Current: N/A; Rtd Power: 0.063W; Rtd Voltage: 50V; Status: Released; Type: Resistor; Vendor: VISHAY; Vendor Part Number: CRCW040222K0JNED; Vendor Part Status: Active; WEIGHT: 0.00065g
R122 = RESISTOR: RESISTOR, THICK FILM, 0.22, -1%/+1%, 0.125W, -55DEGC/+155DEGC, 0402, SMD; ALT_SYMBOLS: RESC1005X50A2L,RESC1005X50A2M; Additional Datasheet URL: N/A; AutoDoc File: https://notefied-dynamic-precision.com/DB/Apps/Desktop/Item/Object.aspx?id=97731; BU Name: DYNAMIC PRECISION GDANSK; Budget Currency: EUR; Budget Price: 0.291; Budgetary Price: 0.291 EUR; Client Status: UNDER_REVIEW; Country of Origin: Israel; Datasheet URL: http://www.vishay.com/docs/20019/rcwe.pdf; Datasheet URL 1: http://www.vishay.com/docs/20019/rcwe.pdf; Datasheet URL 2: N/A; Lead Time: 10; Mass: 0.0007g; Max Oper Temp: +155DEGC; Max TC: +100PPM/DEGC; Max Tol: +1%; Maximum Operating Temperature: +155DEGC; Maximum Temperature Coefficient: +100PPM/DEGC; Maximum Tolerance: +1%; Min Oper Temp: -55DEGC; Min TC: -100PPM/DEGC; Min Tol: -1%; Minimum Operating Temperature: -55DEGC; Minimum Temperature Coeficient: -100PPM/DEGC; Minimum Tolerance: -1%; Mounting Type: SMD; NOTEfied URL: https://notefied-dynamic-precision.com/NOTEfiedWebInterface/part/show?partNumber=01-20687; PCB Package: 0402; Packing Size: 10000; Packing Type: Tape & Reel; Part Number: 01-20687; Part Type: Resistor|0402|LOW RESISTANCE|PRECISION; REACH/SVHC Compliance: Compliant; REACH/SVHC Details: SVHC List Version Jan 12, 2017; REACH/SVHC Source: REACH Declaration; REACH/SVHC Status: Unaffected; ROHS: Exempt; Rated Current: N/A; Rated Power: 0.125W; Rated Voltage: N/A; Resistor Type: THICK FILM; Revision: R008; RoHS Status: ROHS_COMPLIANT_WITH_EXEMPTION; Rtd Current: N/A; Rtd Power: 0.125W; Rtd Voltage: N/A; Status: Released; Texas Part Status: Under Review; Type: Resistor; Vendor: VISHAY; Vendor Part Number: RCWE0402R220FKEA; Vendor Part Status: Active; Weight: 0.0007g
R123 = RESISTOR: RESISTOR, THICK FILM, 82, -1%/+1%, 0.25W, 200V, -55DEGC/+155DEGC, 1206, SMD; ALT_SYMBOLS: RESC3216X75A2L,RESC3216X75A2M; Additional Datasheet URL: N/A; AutoDoc File: https://notefied-dynamic-precision.com/DB/Apps/Desktop/Item/Object.aspx?id=61724; BU Name: DYNAMIC PRECISION GDANSK; Budget Currency: EUR; Budget Price: 0.008; Budgetary Price: 0.008 EUR; Client Status: UNDER_REVIEW; Country of Origin: Israel; Datasheet URL: http://www.vishay.com/docs/20035/dcrcwe3.pdf; Datasheet URL 1: http://www.vishay.com/docs/20035/dcrcwe3.pdf; Datasheet URL 2: N/A; Lead Time: 12; Mass: 0.010g; Max Oper Temp: +155DEGC; Max TC: +100PPM/DEGC; Max Tol: +1%; Maximum Operating Temperature: +155DEGC; Maximum Temperature Coefficient: +100PPM/DEGC; Maximum Tolerance: +1%; Min Oper Temp: -55DEGC; Min TC: -100PPM/DEGC; Min Tol: -1%; Minimum Operating Temperature: -55DEGC; Minimum Temperature Coeficient: -100PPM/DEGC; Minimum Tolerance: -1%; Mounting Type: SMD; NOTEfied URL: https://notefied-dynamic-precision.com/NOTEfiedWebInterface/part/show?partNumber=01-06917; PCB Package: 1206; Packing Size: 5000; Packing Type: Tape & Reel; Part Number: 01-06917; Part Type: Resistor|1206|PRECISION; REACH/SVHC Compliance: Compliant; REACH/SVHC Details: SVHC List Version Jun 20, 2016; REACH/SVHC Source: Material Declaration; REACH/SVHC Status: Unaffected; ROHS: Exempt; Rated Current: N/A; Rated Power: 0.25W; Rated Voltage: 200V; Resistor Type: THICK FILM; Revision: R007; RoHS Status: ROHS_COMPLIANT_WITH_EXEMPTION; Rtd Current: N/A; Rtd Power: 0.25W; Rtd Voltage: 200V; Status: Released; Texas Part Status: Under Review; Type: Resistor; Vendor: VISHAY; Vendor Part Number: CRCW120682R0FKEA; Vendor Part Status: Active; Weight: 0.010g
R125 = RESISTOR: RESISTOR, THICK FILM, 36.5, -1%/+1%, 0.5W, 200V, -55DEGC/+155DEGC, 1210, SMD; ALT_SYMBOLS: RESC3225X75A2L,RESC3225X75A2M; Additional Datasheet URL: N/A; AutoDoc File: https://notefied-dynamic-precision.com/DB/Apps/Desktop/Item/Object.aspx?id=62122; BU Name: DYNAMIC PRECISION GDANSK; Budget Currency: USD; Budget Price: 0.0167; Budgetary Price: 0.0167 USD; Country of Origin: Missing Info; Datasheet URL: http://www.vishay.com/docs/20035/dcrcwe3.pdf; Datasheet URL 1: http://www.vishay.com/docs/20035/dcrcwe3.pdf; Datasheet URL 2: N/A; Lead Time: 10; Mass: 0.016g; Max Oper Temp: +155DEGC; Max TC: +100PPM/DEGC; Max Tol: +1%; Maximum Operating Temperature: +155DEGC; Maximum Temperature Coefficient: +100PPM/DEGC; Maximum Tolerance: +1%; Min Oper Temp: -55DEGC; Min TC: -100PPM/DEGC; Min Tol: -1%; Minimum Operating Temperature: -55DEGC; Minimum Temperature Coeficient: -100PPM/DEGC; Minimum Tolerance: -1%; Mounting Type: SMD; NOTEfied URL: https://notefied-dynamic-precision.com/NOTEfiedWebInterface/part/show?partNumber=01-07315; PCB Package: 1210; Packing Size: 5000; Packing Type: Tape & Reel; Part Number: 01-07315; Part Type: Resistor|1210|PRECISION; REACH/SVHC Compliance: Compliant; REACH/SVHC Details: SVHC List Version Jun 20, 2016; REACH/SVHC Source: Material Declaration; REACH/SVHC Status: Unaffected; ROHS: Exempt; Rated Current: N/A; Rated Power: 0.5W; Rated Voltage: 200V; Resistor Type: THICK FILM; Revision: R006; RoHS Status: ROHS_COMPLIANT; Rtd Current: N/A; Rtd Power: 0.5W; Rtd Voltage: 200V; Status: Released; Texas Part Status: Under Review; Type: Resistor; Vendor: VISHAY; Vendor Part Number: CRCW121036R5FKEA; Vendor Part Status: Active; Weight: 0.016g
R126 = RESISTOR: RESISTOR, THICK FILM, 4.7k, -5%/+5%, 0.063W, 50V, -55DEGC/+155DEGC, 0402, SMD; Additional Datasheet URL: N/A; AutoDoc File: https://notefied-dynamic-precision.com/DB/Apps/Desktop/Item/Object.aspx?id=113326; BU Name: TEXAS INSTRUMENTS NORWAY; Budget Currency: EUR; Budget Price: 0.014; Budgetary Price: 0.014 EUR; Client Status: UNDER_REVIEW; Country of Origin: Israel; Datasheet URL: http://www.vishay.com/docs/20035/dcrcwe3.pdf; Datasheet URL 1: http://www.vishay.com/docs/20035/dcrcwe3.pdf; Datasheet URL 2: N/A; Definied Quality: INDUSTRIAL; Esd Level: N/A; Exclusive for Customers: TEXAS INSTRUMENTS NORWAY; Lead Time: 18; LifeCycle Status: ACTIVE; MPN: RESISTOR_0402_10k_+/-5%_50V_0.063W_M_+/-200ppm; MPN Status: ACTIVE; MSL: N/A; MTBF: N/A; MTBF Standard: N/A; Manufacturer: MANUFACTURER SELECTION; Mass: 0.00065g; Max Oper Temp: +155DEGC; Max TC: +200PPM/DEGC; Max Tol: +5%; Maximum Operating Temperature: +155DEGC; Maximum Temperature Coefficient: +200PPM/DEGC; Maximum Tolerance: +5%; Min Oper Temp: -55DEGC; Min TC: -200PPM/DEGC; Min Tol: -5%; Minimum Operating Temperature: -55DEGC; Minimum Temperature Coeficient: -200PPM/DEGC; Minimum Tolerance: -5%; Mounting Type: SMD; NOTE Status: PREFERRED; NOTEfied URL: https://notefied-dynamic-precision.com/NOTEfiedWebInterface/part/show?partNumber=01-22489; Notes: Standard item: Duplicate Reason: custom footprint for TEXAS INSTRUMENTS NORWAY.; Old Footprint: RESC1005X40N; PCB Package: 0402; Packing Size: 10000; Packing Type: Tape & Reel; Part Number: 01-22489; Part Type: Resistor|0402|STANDARD; REACH/SVHC Compliance: Compliant; REACH/SVHC Details: SVHC List Version Jun 20, 2016; REACH/SVHC Source: Material Declaration; REACH/SVHC Status: Unaffected; REACH/SVHC_COMPLIANCE: COMPLIANT; REACH/SVHC_DETAILS: SVHC LIST VERSION Jun 20, 2016; REACH/SVHC_SOURCE: MATERIAL DECLARATION; REACH/SVHC_STATUS: UNAFFECTED; ROHS: Exempt; Rated Current: N/A; Rated Power: 0.063W; Rated Voltage: 50V; Resistor Type: THICK FILM; Revision: R007; RoHS Status: ROHS_COMPLIANT_WITH_EXEMPTION; Rtd Current: N/A; Rtd Power: 0.063W; Rtd Voltage: 50V; Status: Released; Texas Part Status: Under Review; Type: Resistor; Vendor: VISHAY; Vendor Part Number: CRCW04024K70JNED; Vendor Part Status: Active; WEIGHT: 0.00065g
R127-R129 = RESISTOR: RESISTOR, THICK FILM, 47k, -5%/+5%, 0.063W, 50V, -55DEGC/+155DEGC, 0402, SMD; ALT_SYMBOLS: RESC1005X40A2L,RESC1005X40A2M; Additional Datasheet URL: N/A; AutoDoc File: https://notefied-dynamic-precision.com/DB/Apps/Desktop/Item/Object.aspx?id=47144; BU Name: DYNAMIC PRECISION GDANSK; Budget Currency: EUR; Budget Price: 0.014; Budgetary Price: 0.014 EUR; Country of Origin: Mexico; Datasheet URL: http://www.vishay.com/docs/20035/dcrcwe3.pdf; Datasheet URL 1: http://www.vishay.com/docs/20035/dcrcwe3.pdf; Datasheet URL 2: N/A; Lead Time: 18; Mass: 0.00065g; Max Oper Temp: +155DEGC; Max TC: +200PPM/DEGC; Max Tol: +5%; Maximum Operating Temperature: +155DEGC; Maximum Temperature Coefficient: +200PPM/DEGC; Maximum Tolerance: +5%; Min Oper Temp: -55DEGC; Min TC: -200PPM/DEGC; Min Tol: -5%; Minimum Operating Temperature: -55DEGC; Minimum Temperature Coeficient: -200PPM/DEGC; Minimum Tolerance: -5%; Mounting Type: SMD; NOTEfied URL: https://notefied-dynamic-precision.com/NOTEfiedWebInterface/part/show?partNumber=01-01260; PCB Package: 0402; Packing Size: 10000; Packing Type: Tape & Reel; Part Number: 01-01260; Part Type: Resistor|0402|STANDARD; REACH/SVHC Compliance: Compliant; REACH/SVHC Details: SVHC List Version Jun 20, 2016; REACH/SVHC Source: Material Declaration; REACH/SVHC Status: Unaffected; ROHS: Exempt; Rated Current: N/A; Rated Power: 0.063W; Rated Voltage: 50V; Resistor Type: THICK FILM; Revision: R006; RoHS Status: ROHS_COMPLIANT; Rtd Current: N/A; Rtd Power: 0.063W; Rtd Voltage: 50V; Status: Released; Texas Part Status: Under Review; Type: Resistor; Vendor: VISHAY; Vendor Part Number: CRCW040247K0JNED; Vendor Part Status: Active; Weight: 0.00065g
R130 = RESISTOR: RESISTOR, THICK FILM, 2.2k, -1%/+1%, 0.063W, 50V, -55DEGC/+155DEGC, 0402, SMD; ALT_SYMBOLS: RESC1005X40A2L,RESC1005X40A2M; Additional Datasheet URL: N/A; AutoDoc File: https://notefied-dynamic-precision.com/DB/Apps/Desktop/Item/Object.aspx?id=46123; BU Name: DYNAMIC PRECISION GDANSK; Budget Currency: EUR; Budget Price: 0.012; Budgetary Price: 0.012 EUR; Client Status: UNDER_REVIEW; Country of Origin: Israel; Datasheet URL: http://www.vishay.com/docs/20035/dcrcwe3.pdf; Datasheet URL 1: http://www.vishay.com/docs/20035/dcrcwe3.pdf; Datasheet URL 2: N/A; Lead Time: 14; Mass: 0.00060916g; Max Oper Temp: +155DEGC; Max TC: +100PPM/DEGC; Max Tol: +1%; Maximum Operating Temperature: +155DEGC; Maximum Temperature Coefficient: +100PPM/DEGC; Maximum Tolerance: +1%; Min Oper Temp: -55DEGC; Min TC: -100PPM/DEGC; Min Tol: -1%; Minimum Operating Temperature: -55DEGC; Minimum Temperature Coeficient: -100PPM/DEGC; Minimum Tolerance: -1%; Mounting Type: SMD; NOTEfied URL: https://notefied-dynamic-precision.com/NOTEfiedWebInterface/part/show?partNumber=01-00239; PCB Package: 0402; Packing Size: 10000; Packing Type: Tape & Reel; Part Number: 01-00239; Part Type: Resistor|0402|PRECISION; REACH/SVHC Compliance: Compliant; REACH/SVHC Details: SVHC List Version Jun 20, 2016; REACH/SVHC Source: Material Declaration; REACH/SVHC Status: Unaffected; ROHS: Exempt; Rated Current: N/A; Rated Power: 0.063W; Rated Voltage: 50V; Resistor Type: THICK FILM; Revision: R013; RoHS Status: ROHS_COMPLIANT_WITH_EXEMPTION; Rtd Current: N/A; Rtd Power: 0.063W; Rtd Voltage: 50V; Status: Released; Texas Part Status: Under Review; Type: Resistor; Vendor: VISHAY; Vendor Part Number: CRCW04022K20FKED; Vendor Part Status: Active; Weight: 0.00060916g
R131 = RESISTOR: RESISTOR, THICK FILM, 0, 0.063W, 50V, -55DEGC/+155DEGC, 0402, SMD; Additional Datasheet URL: N/A; AutoDoc File: https://notefied-dynamic-precision.com/DB/Apps/Desktop/Item/Object.aspx?id=47959; BU Name: DYNAMIC PRECISION GDANSK; Budget Currency: EUR; Budget Price: 0.012; Budgetary Price: 0.007 EUR; Client Status: UNDER_REVIEW; Country of Origin: Israel; Datasheet URL: http://www.vishay.com/docs/20035/dcrcwe3.pdf; Datasheet URL 1: http://www.vishay.com/docs/20035/dcrcwe3.pdf; Datasheet URL 2: N/A; Exclusive for Customers: TEXAS INSTRUMENTS NORWAY; Lead Time: 14; Mass: 0.0006152g; Max Oper Temp: +155DEGC; Max TC: +100PPM/DEGC; Max Tol: +1%; Maximum Operating Temperature: +155DEGC; Maximum Temperature Coefficient: N/A; Maximum Tolerance: N/A; Min Oper Temp: -55DEGC; Min TC: -100PPM/DEGC; Min Tol: -1%; Minimum Operating Temperature: -55DEGC; Minimum Temperature Coeficient: N/A; Minimum Tolerance: N/A; Mounting Type: SMD; NOTEfied URL: https://notefied-dynamic-precision.com/NOTEfiedWebInterface/part/show?partNumber=01-22495; Notes: Standard item: Duplicate Reason: custom footprint for TEXAS INSTRUMENTS NORWAY.; PCB Package: 0402; Packing Size: 10000; Packing Type: Tape & Reel; Part Number: 01-22495; Part Type: Resistor|0402|JUMPER; REACH/SVHC Compliance: Compliant; REACH/SVHC Details: SVHC List Version Jul 07, 2017; REACH/SVHC Source: REACH Declaration; REACH/SVHC Status: Unaffected; ROHS: Exempt; Rated Current: N/A; Rated Power: 0.063W; Rated Voltage: 50V; Resistor Type: THICK FILM; Revision: R012; RoHS Status: ROHS_COMPLIANT_WITH_EXEMPTION; Rtd Current: N/A; Rtd Power: 0.063W; Rtd Voltage: 50V; Status: Released; Texas Part Status: Under Review; Type: Resistor; Vendor: VISHAY; Vendor Part Number: CRCW04020000Z0ED; Vendor Part Status: Active; Weight: 0.00060916g
R137 = RESISTOR: RESISTOR, THICK FILM, 2.61k, -1%/+1%, 0.063W, 50V, -55DEGC/+155DEGC, 0402, SMD; ALT_SYMBOLS: RESC1005X40A2L,RESC1005X40A2M; Additional Datasheet URL: N/A; Budgetary Price: 0.016 EUR; Country of Origin: Israel; Datasheet URL: http://www.vishay.com/docs/20035/dcrcwe3.pdf; Lead Time: 18; Mass: 0.00065g; Maximum Operating Temperature: +155DEGC; Maximum Temperature Coefficient: +100PPM/DEGC; Maximum Tolerance: +1%; Minimum Operating Temperature: -55DEGC; Minimum Temperature Coeficient: -100PPM/DEGC; Minimum Tolerance: -1%; Mounting Type: SMD; NOTEfied URL: https://notefied-dynamic-precision.com/NOTEfiedWebInterface/part/show?partNumber=01-04542; PCB Package: 0402; Packing Size: 10000; Packing Type: Tape & Reel; Part Number: 01-04542; Part Type: Resistor|0402|PRECISION; REACH/SVHC Compliance: Compliant; REACH/SVHC Details: SVHC List Version Jun 20, 2016; REACH/SVHC Source: Material Declaration; REACH/SVHC Status: Unaffected; ROHS: Exempt; Rated Current: N/A; Rated Power: 0.063W; Rated Voltage: 50V; Resistor Type: THICK FILM; Revision: R006; Status: Released; Texas Part Status: Under Review; Type: Resistor; Vendor: VISHAY; Vendor Part Number: CRCW04022K61FKED; Vendor Part Status: Active
